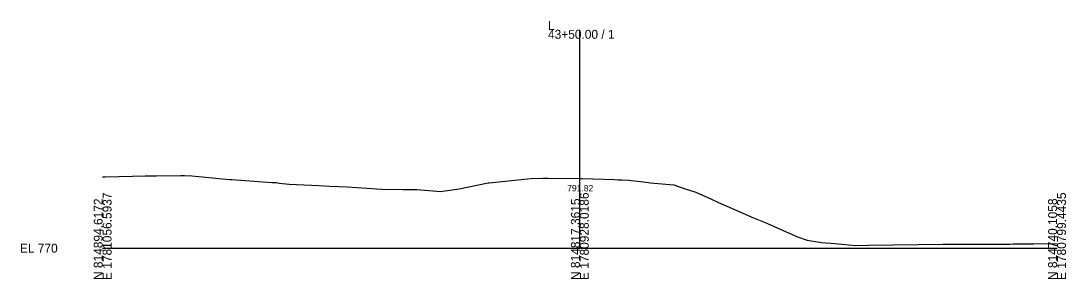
# Model space of a CAD drawing. Extents: x -26 to 7903, y -10 to 9573.
# Drawn here: x 974.3 to 1302.8, y 4490.3 to 4571.3 of the extents above; entities that cross this region are included whole.
import ezdxf

# ---------------------------------------------------------------- set-up
doc = ezdxf.new("R2010")
doc.units = 0
for name, color, linetype in [('Exist Cross Section Cell', 7, 'Continuous'), ('Exist XS Center Line Elevation Label', 7, 'Continuous'), ('Exist XS Ground Line', 7, 'Continuous')]:
    doc.layers.add(name, color=color, linetype=linetype)

msp = doc.modelspace()

# ---------------------------------------------------------------- linework, layer by layer
at = {"layer": 'Exist Cross Section Cell'}
for p, q in [((1150, 4500), (1150, 4568.52)), ((1000, 4500), (1150, 4500)), ((1150, 4500), (1300, 4500))]:
    msp.add_line(p, q, dxfattribs=at)
at = {"layer": 'Exist XS Ground Line'}
for p, q in [((1000, 4522.37), (1000.81, 4522.41)), ((1000.81, 4522.41), (1009.38, 4522.6)), ((1009.38, 4522.6), (1013.37, 4522.69)), ((1013.37, 4522.69), (1016.88, 4522.74)), ((1016.88, 4522.74), (1024.59, 4522.84)), ((1024.59, 4522.84), (1025.74, 4522.79)), ((1025.74, 4522.79), (1028.06, 4522.7)), ((1028.06, 4522.7), (1039.88, 4521.6)), ((1039.88, 4521.6), (1040.61, 4521.54)), ((1040.61, 4521.54), (1043.43, 4521.34)), ((1043.43, 4521.34), (1053.17, 4520.61)), ((1053.17, 4520.61), (1054.68, 4520.56)), ((1121.5, 4520.52), (1133.57, 4521.73)), ((1133.57, 4521.73), (1134.69, 4521.82)), ((1134.69, 4521.82), (1138.49, 4521.97)), ((1138.49, 4521.97), (1139.21, 4521.96)), ((1139.21, 4521.96), (1140.02, 4521.95)), ((1140.02, 4521.95), (1150, 4521.82)), ((1150, 4521.82), (1150.72, 4521.82)), ((1150.72, 4521.82), (1160.92, 4521.51)), ((1160.92, 4521.51), (1162.05, 4521.48)), ((1162.05, 4521.48), (1163.3, 4521.44)), ((1163.3, 4521.44), (1165.35, 4521.33)), ((1165.35, 4521.33), (1166.05, 4521.29)), ((1166.05, 4521.29), (1168.19, 4521.02)), ((1168.19, 4521.02), (1171.59, 4520.59)), ((1054.68, 4520.56), (1055.48, 4520.45)), ((1055.48, 4520.45), (1057.56, 4520.16)), ((1057.56, 4520.16), (1058.64, 4520.13)), ((1058.64, 4520.13), (1067.92, 4519.68)), ((1067.92, 4519.68), (1071.37, 4519.49)), ((1071.37, 4519.49), (1076.87, 4519.2)), ((1076.87, 4519.2), (1087.67, 4518.56)), ((1087.67, 4518.56), (1094.37, 4518.46)), ((1094.37, 4518.46), (1098.79, 4518.41)), ((1098.79, 4518.41), (1106.29, 4517.74)), ((1106.29, 4517.74), (1107.64, 4517.95)), ((1107.64, 4517.95), (1112.06, 4518.65)), ((1112.06, 4518.65), (1114.55, 4519.16)), ((1114.55, 4519.16), (1121.16, 4520.48)), ((1121.16, 4520.48), (1121.5, 4520.52)), ((1171.59, 4520.59), (1172.12, 4520.54)), ((1172.12, 4520.54), (1179.58, 4519.84)), ((1179.58, 4519.84), (1182.51, 4518.8)), ((1182.51, 4518.8), (1186.47, 4517.61)), ((1186.47, 4517.61), (1191.4, 4515.33)), ((1191.4, 4515.33), (1193.57, 4514.3)), ((1193.57, 4514.3), (1204.54, 4509.52)), ((1204.54, 4509.52), (1207.21, 4508.51)), ((1207.21, 4508.51), (1208.21, 4508.06)), ((1208.21, 4508.06), (1218.41, 4503.61)), ((1218.41, 4503.61), (1221.45, 4502.56)), ((1221.45, 4502.56), (1225.36, 4501.85)), ((1225.36, 4501.85), (1225.92, 4501.74)), ((1225.92, 4501.74), (1230.1, 4501.47)), ((1230.1, 4501.47), (1236.75, 4500.85)), ((1236.75, 4500.85), (1240.76, 4500.92)), ((1240.76, 4500.92), (1264.08, 4501.29)), ((1264.08, 4501.29), (1277.11, 4501.26)), ((1277.11, 4501.26), (1285.28, 4501.31)), ((1285.28, 4501.31), (1286.17, 4501.34)), ((1286.17, 4501.34), (1292.68, 4501.41)), ((1292.68, 4501.41), (1300, 4501.47))]:
    msp.add_line(p, q, dxfattribs=at)

# ---------------------------------------------------------------- texts
at = {"layer": 'Exist Cross Section Cell'}
for s, p in [('L', (1140, 4568.52)), ('43+50.00 / 1', (1140, 4565.72)), ('EL 770', (974, 4498.6))]:
    msp.add_text(s, height=2.8, dxfattribs=at).set_placement(p)
for s, p in [('E 1780799.4435', (1302.8, 4490)), ('N 814894.6172', (1000, 4490)), ('E 1781056.5937', (1002.8, 4490)), ('N 814817.3615', (1150, 4490)), ('E 1780928.0186', (1152.8, 4490)), ('N 814740.1058', (1300, 4490))]:
    msp.add_text(s, height=2.8, rotation=90, dxfattribs=at).set_placement(p)
at = {"layer": 'Exist XS Center Line Elevation Label'}
msp.add_text('791.82', height=2, dxfattribs=at).set_placement((1146.03, 4517.82))

doc.saveas('drawing.dxf')
